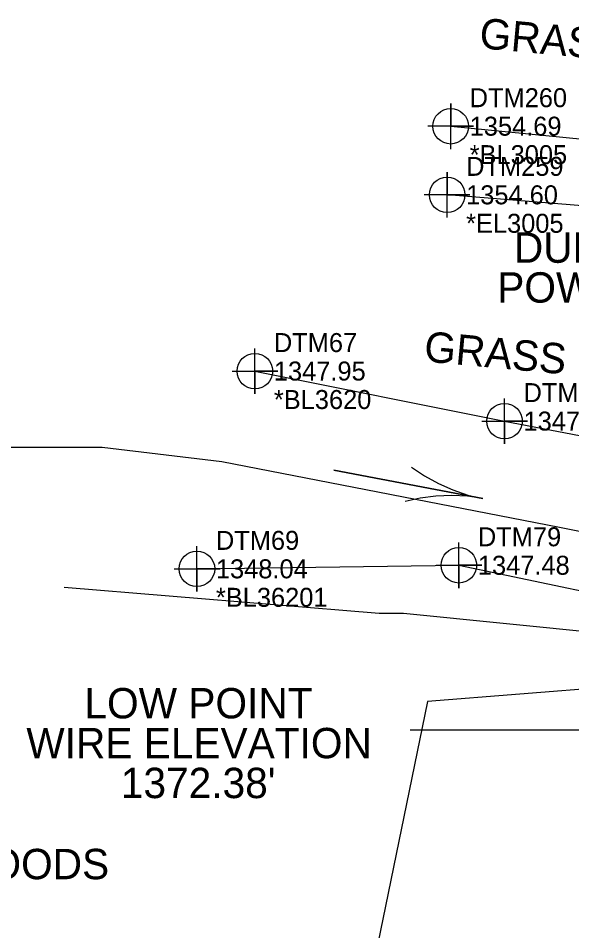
# Model space of a CAD drawing. Extents: x 1251492 to 1253015, y 859607 to 860610.
# Drawn here: x 1251900 to 1251972.9, y 859984.8 to 860105 of the extents above; entities that cross this region are included whole.
import ezdxf

# ---------------------------------------------------------------- set-up
doc = ezdxf.new("R2010")
doc.units = 0
for name, color, linetype in [('Exist Hydro Jurisdictional Stream or Body of Water', 7, 'Continuous'), ('Exist Hydro River Flow Arrow CELL', 7, 'Continuous'), ('Exist Hydro Stream or Body of Water Cogo Comment', 7, 'Continuous'), ('Exist Hydro Stream or Body of Water Cogo Elevation', 7, 'Continuous'), ('Exist Hydro Stream or Body of Water Cogo Number', 7, 'Continuous'), ('Exist Hydro Stream or Body of Water Cogo Point CELL', 7, 'Continuous'), ('Exist Other Culture Located Object Leader', 7, 'Continuous'), ('Exist Other Culture Located Object Text', 7, 'Continuous'), ('Exist Property Line', 7, 'Continuous'), ('Exist Roads Soil', 7, 'Continuous'), ('Exist Roads Soil Cogo Comment', 7, 'Continuous'), ('Exist Roads Soil Cogo Elevation', 7, 'Continuous'), ('Exist Roads Soil Cogo Number', 7, 'Continuous'), ('Exist Roads Soil Cogo Point CELL', 7, 'Continuous'), ('Exist Utilities Power Pole Text', 7, 'Continuous'), ('Exist Vegetation Woods Line', 7, 'Continuous'), ('Exist Vegetation Woods Line Text', 7, 'Continuous')]:
    doc.layers.add(name, color=color, linetype=linetype)

msp = doc.modelspace()

# ---------------------------------------------------------------- linework, layer by layer
at = {"layer": 'Exist Hydro Jurisdictional Stream or Body of Water'}
for points in [[(1251931.15, 860058.53), (1251964.01, 860051.94), (1251993.85, 860046.21), (1252023.88, 860040.56), (1252026.12, 860039.99)], [(1251923.52, 860032.49), (1251958, 860032.96), (1251987.7, 860026.74), (1252004.41, 860018.88), (1252004.61, 860014.58), (1251994.72, 860013.05), (1252010.92, 860007.68), (1252019.46, 860003.97), (1252019.67, 860004.2), (1252025.03, 860004.06)]]:
    msp.add_lwpolyline(points, dxfattribs=at)
at = {"layer": 'Exist Hydro River Flow Arrow CELL'}
msp.add_line((1251951.35, 860043.61), (1251951.35, 860043.61), dxfattribs=at)
msp.add_lwpolyline([(1251951.78, 860045.86), (1251953.48, 860044.73), (1251955.3, 860043.74), (1251957.21, 860042.89), (1251959.17, 860042.2), (1251961.17, 860041.74), (1251941.52, 860045.49), (1251961.17, 860041.74), (1251959.14, 860042.05), (1251957.07, 860042.13), (1251954.98, 860042.04), (1251952.92, 860041.79), (1251950.92, 860041.37)], dxfattribs=at)
at = {"layer": 'Exist Hydro Stream or Body of Water Cogo Point CELL'}
for points in [[(1251928.15, 860058.53), (1251934.15, 860058.53), (1251931.15, 860058.53), (1251931.15, 860055.53), (1251931.15, 860061.53)], [(1251961.01, 860051.94), (1251967.01, 860051.94), (1251964.01, 860051.94), (1251964.01, 860048.94), (1251964.01, 860054.94)], [(1251955, 860032.96), (1251961, 860032.96), (1251958, 860032.96), (1251958, 860029.96), (1251958, 860035.96)], [(1251920.52, 860032.49), (1251926.52, 860032.49), (1251923.52, 860032.49), (1251923.52, 860029.49), (1251923.52, 860035.49)]]:
    msp.add_lwpolyline(points, dxfattribs=at)
for centre in [(1251931.15, 860058.53), (1251964.01, 860051.94), (1251923.52, 860032.49), (1251958, 860032.96)]:
    msp.add_circle(centre, 2.34, dxfattribs=at)
at = {"layer": 'Exist Other Culture Located Object Leader'}
msp.add_line((1251979.48, 860011.24), (1251951.58, 860011.24), dxfattribs=at)
at = {"layer": 'Exist Property Line'}
for p, q in [((1251911.04, 860048.45), (1251879.56, 860048.45)), ((1251926.79, 860046.6), (1251911.04, 860048.45)), ((1251971.25, 860037.95), (1251926.79, 860046.6)), ((1252024.35, 860026.96), (1251971.25, 860037.95))]:
    msp.add_line(p, q, dxfattribs=at)
at = {"layer": 'Exist Roads Soil'}
for points in [[(1251956.92, 860090.78), (1251999.35, 860086.64), (1252028.3, 860088.86), (1252043.49, 860095.85), (1252053.21, 860097.1)], [(1252027.15, 860067.33), (1252015.44, 860074.92), (1251989.36, 860079.09), (1251956.45, 860081.75)]]:
    msp.add_lwpolyline(points, dxfattribs=at)
at = {"layer": 'Exist Roads Soil Cogo Point CELL'}
for points in [[(1251956.92, 860087.78), (1251956.92, 860093.78), (1251956.92, 860090.78), (1251959.92, 860090.78), (1251953.92, 860090.78)], [(1251956.45, 860078.75), (1251956.45, 860084.75), (1251956.45, 860081.75), (1251959.45, 860081.75), (1251953.45, 860081.75)]]:
    msp.add_lwpolyline(points, dxfattribs=at)
for centre in [(1251956.92, 860090.78), (1251956.45, 860081.75)]:
    msp.add_circle(centre, 2.34, dxfattribs=at)
at = {"layer": 'Exist Vegetation Woods Line'}
msp.add_lwpolyline([(1251906.04, 860030.07), (1251947.52, 860026.63), (1251950.69, 860026.63), (1251977.37, 860023.99), (1251990.31, 860017.91), (1251953.86, 860015.01), (1251946.99, 859981.44), (1251967.59, 859939.16), (1251997.44, 859888.41), (1252000.35, 859873.88), (1251996.91, 859863.57), (1251974.99, 859868.07), (1251962.31, 859871.5), (1251952.54, 859855.91), (1251959.4, 859825.52), (1251974.99, 859768.96), (1251988.99, 859729.85)], dxfattribs=at)

# ---------------------------------------------------------------- texts
at = {"layer": 'Exist Hydro Stream or Body of Water Cogo Comment'}
for s, p in [('*BL3620', (1251933.65, 860053.54)), ('*BL36201', (1251926.02, 860027.49))]:
    msp.add_text(s, height=2.5, dxfattribs=at).set_placement(p)
at = {"layer": 'Exist Hydro Stream or Body of Water Cogo Elevation'}
for s, p in [('1347.95', (1251933.65, 860057.29)), ('1347.68', (1251966.51, 860050.7)), ('1348.04', (1251926.02, 860031.24)), ('1347.48', (1251960.5, 860031.71))]:
    msp.add_text(s, height=2.5, dxfattribs=at).set_placement(p)
at = {"layer": 'Exist Hydro Stream or Body of Water Cogo Number'}
for s, p in [('DTM67', (1251933.65, 860061.04)), ('DTM84', (1251966.51, 860054.45)), ('DTM69', (1251926.02, 860034.99)), ('DTM79', (1251960.5, 860035.46))]:
    msp.add_text(s, height=2.5, dxfattribs=at).set_placement(p)
at = {"layer": 'Exist Other Culture Located Object Text'}
for s, p in [('LOW POINT', (1251908.72, 860012.79)), ('WIRE ELEVATION', (1251901.07, 860007.54)), ("1372.38'", (1251913.51, 860002.29))]:
    msp.add_text(s, height=4, dxfattribs=at).set_placement(p)
at = {"layer": 'Exist Roads Soil Cogo Comment'}
for s, p in [('*BL3005', (1251959.42, 860085.79)), ('*EL3005', (1251958.95, 860076.75))]:
    msp.add_text(s, height=2.5, dxfattribs=at).set_placement(p)
at = {"layer": 'Exist Roads Soil Cogo Elevation'}
for s, p in [('1354.69', (1251959.42, 860089.54)), ('1354.60', (1251958.95, 860080.5))]:
    msp.add_text(s, height=2.5, dxfattribs=at).set_placement(p)
at = {"layer": 'Exist Roads Soil Cogo Number'}
for s, p in [('DTM260', (1251959.42, 860093.29)), ('DTM259', (1251958.95, 860084.25))]:
    msp.add_text(s, height=2.5, dxfattribs=at).set_placement(p)
at = {"layer": 'Exist Utilities Power Pole Text'}
for s, p in [('DUKE', (1251965.24, 860072.8)), ('POWER', (1251963.05, 860067.55))]:
    msp.add_text(s, height=4, dxfattribs=at).set_placement(p)
at = {"layer": 'Exist Vegetation Woods Line Text'}
for p in [(1251960.59, 860101.08), (1251953.31, 860059.81)]:
    msp.add_text('GRASS', height=4, rotation=354.7669, dxfattribs=at).set_placement(p)
msp.add_text('WOODS', height=4, dxfattribs=at).set_placement((1251891.17, 859991.61))

doc.saveas('drawing.dxf')
